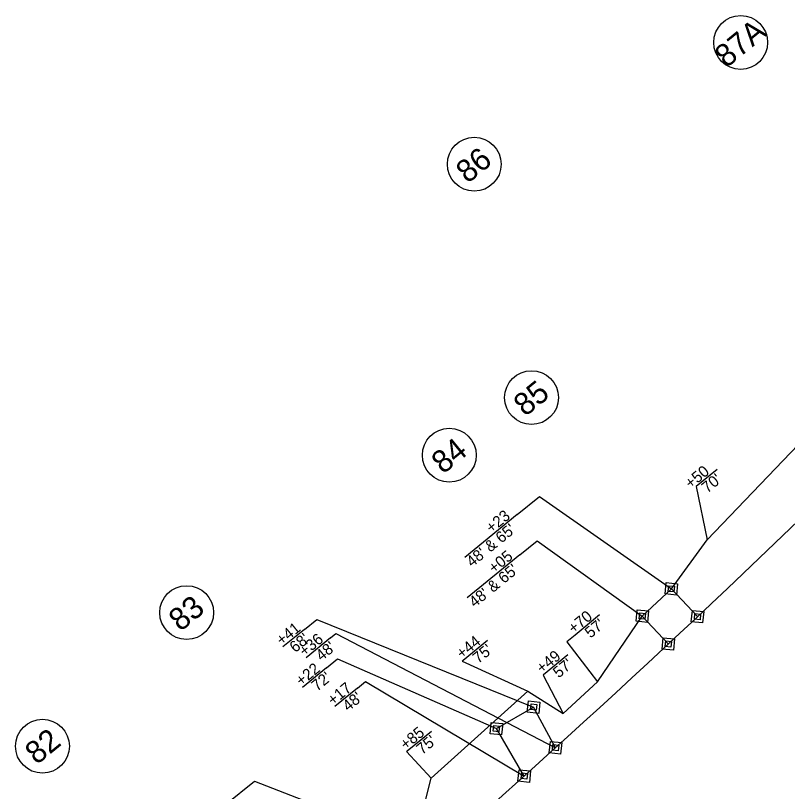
# Model space of a CAD drawing. Extents: x 2320946 to 2332748, y 597838 to 612698.
# Drawn here: x 2326768.2 to 2327112.4, y 602415.6 to 602761.5 of the extents above; entities that cross this region are included whole.
import ezdxf

# ---------------------------------------------------------------- set-up
doc = ezdxf.new("R2010")
doc.units = 0
for name, color, linetype in [('Prop Easement Construction', 7, 'Continuous'), ('Prop Easement Construction Station Offsets', 7, 'Continuous'), ('Prop Easement Permanent Drainage', 7, 'Continuous'), ('Prop Easement Permanent Drainage Station Offsets', 7, 'Continuous'), ('Prop Parcel Number CELL', 7, 'Continuous'), ('Prop ROW Marker CELL', 7, 'Continuous'), ('Prop ROW Permanent Easement CELL', 7, 'Continuous'), ('Prop ROW RW Lines', 7, 'Continuous')]:
    doc.layers.add(name, color=color, linetype=linetype)

msp = doc.modelspace()

# ---------------------------------------------------------------- linework, layer by layer
at = {"layer": 'Prop Easement Construction'}
for p, q in [((2327076.54, 602527.84), (2327251.95, 602710.54)), ((2327060.63, 602505.91), (2327076.54, 602527.84)), ((2327028.65, 602494.3), (2327017.68, 602485.34)), ((2327027.74, 602464.41), (2327047.66, 602493.77)), ((2326978.66, 602482.95), (2326967.74, 602474.04)), ((2327014.46, 602476.53), (2327003.59, 602467.65)), ((2327012.44, 602450.38), (2327027.74, 602464.41)), ((2326953.47, 602421.5), (2326996.67, 602460.36)), ((2326996.67, 602460.36), (2327012.44, 602450.38)), ((2326953.61, 602442.39), (2326942.76, 602433.53)), ((2326946.26, 602392.43), (2326953.47, 602421.5))]:
    msp.add_line(p, q, dxfattribs=at)
for points in [[(2327017.68, 602485.34), (2327013.98, 602482.32), (2327027.74, 602464.41)], [(2326967.74, 602474.04), (2326967.28, 602473.66), (2326996.67, 602460.36)], [(2327003.59, 602467.65), (2327003.41, 602467.51), (2327012.44, 602450.38)], [(2326942.76, 602433.53), (2326942.55, 602433.36), (2326953.47, 602421.5)]]:
    msp.add_lwpolyline(points, dxfattribs=at)
at = {"layer": 'Prop Easement Construction Station Offsets'}
msp.add_line((2327081, 602559.15), (2327071.73, 602551.58), dxfattribs=at)
msp.add_lwpolyline([(2327071.73, 602551.58), (2327076.54, 602527.84)], dxfattribs=at)
at = {"layer": 'Prop Easement Permanent Drainage'}
for p, q in [((2327047.66, 602493.77), (2327060.63, 602505.91)), ((2327060.63, 602505.91), (2327072.27, 602493.53)), ((2327047.66, 602493.77), (2327059.26, 602481.34)), ((2326982.62, 602443.59), (2326999.19, 602453.2)), ((2327008.98, 602435.07), (2326999.19, 602453.2)), ((2326995.02, 602422.45), (2326982.62, 602443.59))]:
    msp.add_line(p, q, dxfattribs=at)
at = {"layer": 'Prop Easement Permanent Drainage Station Offsets'}
for p, q in [((2326991.82, 602539.01), (2326968.47, 602519.95)), ((2326993.01, 602521.03), (2326969.65, 602501.96)), ((2326897, 602487.83), (2326887.46, 602480.04)), ((2326908.68, 602484.13), (2326897.79, 602475.23)), ((2326906.79, 602470.64), (2326896.12, 602461.93)), ((2326920.62, 602461.67), (2326910.55, 602453.45))]:
    msp.add_line(p, q, dxfattribs=at)
for points in [[(2326991.82, 602539.01), (2327001.79, 602547.15), (2327060.63, 602505.91)], [(2326993.01, 602521.03), (2327000.8, 602527.39), (2327047.66, 602493.77)], [(2326897, 602487.83), (2326902.51, 602492.33), (2326999.19, 602453.2)], [(2326908.68, 602484.13), (2326911.02, 602486.04), (2327008.98, 602435.07)], [(2326906.79, 602470.64), (2326911.73, 602474.67), (2326982.62, 602443.59)], [(2326920.62, 602461.67), (2326924.3, 602464.68), (2326995.02, 602422.45)], [(2326861.9, 602409.71), (2326874.72, 602420.17), (2326946.26, 602392.43)]]:
    msp.add_lwpolyline(points, dxfattribs=at)
at = {"layer": 'Prop Parcel Number CELL'}
for p, q in [((2327091.52, 602749.54), (2327091.52, 602749.54)), ((2326972.74, 602695.23), (2326972.74, 602695.23)), ((2326998.28, 602591.18), (2326998.28, 602591.18)), ((2326961.61, 602565.5), (2326961.61, 602565.5)), ((2326844.51, 602495.34), (2326844.51, 602495.34)), ((2326780.21, 602435.76), (2326780.21, 602435.76))]:
    msp.add_line(p, q, dxfattribs=at)
for centre in [(2327091.52, 602749.54), (2326972.74, 602695.23), (2326998.28, 602591.18), (2326961.61, 602565.5), (2326844.51, 602495.34), (2326780.21, 602435.76)]:
    msp.add_circle(centre, 12, dxfattribs=at)
at = {"layer": 'Prop ROW Marker CELL'}
for p, q in [((2327060.63, 602505.91), (2327060.63, 602505.91)), ((2327047.66, 602493.77), (2327047.66, 602493.77)), ((2327072.27, 602493.53), (2327072.27, 602493.53)), ((2327059.26, 602481.34), (2327059.26, 602481.34)), ((2326999.19, 602453.2), (2326999.19, 602453.2)), ((2326982.62, 602443.59), (2326982.62, 602443.59)), ((2327008.98, 602435.07), (2327008.98, 602435.07)), ((2326995.02, 602422.45), (2326995.02, 602422.45))]:
    msp.add_line(p, q, dxfattribs=at)
at = {"layer": 'Prop ROW Permanent Easement CELL'}
for points in [[(2327058.35, 602508.7), (2327063.41, 602508.19), (2327062.9, 602503.12), (2327057.84, 602503.64)], [(2327059.49, 602507.31), (2327062.02, 602507.05), (2327061.76, 602504.52), (2327059.23, 602504.77)], [(2327045.38, 602496.56), (2327050.45, 602496.05), (2327049.94, 602490.98), (2327044.87, 602491.49)], [(2327046.52, 602495.16), (2327049.06, 602494.91), (2327048.8, 602492.38), (2327046.27, 602492.63)], [(2327069.99, 602496.32), (2327075.06, 602495.8), (2327074.55, 602490.74), (2327069.48, 602491.25)], [(2327071.13, 602494.92), (2327073.66, 602494.67), (2327073.41, 602492.13), (2327070.88, 602492.39)], [(2327056.98, 602484.13), (2327062.05, 602483.62), (2327061.54, 602478.55), (2327056.47, 602479.06)], [(2327058.12, 602482.74), (2327060.65, 602482.48), (2327060.4, 602479.95), (2327057.87, 602480.2)], [(2326996.92, 602455.99), (2327001.98, 602455.47), (2327001.47, 602450.41), (2326996.4, 602450.92)], [(2326998.05, 602454.59), (2327000.59, 602454.34), (2327000.33, 602451.8), (2326997.8, 602452.06)], [(2326980.35, 602446.38), (2326985.41, 602445.86), (2326984.9, 602440.8), (2326979.84, 602441.31)], [(2326981.49, 602444.98), (2326984.02, 602444.72), (2326983.76, 602442.19), (2326981.23, 602442.45)], [(2327006.71, 602437.86), (2327011.77, 602437.35), (2327011.26, 602432.28), (2327006.19, 602432.79)], [(2327007.84, 602436.46), (2327010.38, 602436.21), (2327010.12, 602433.68), (2327007.59, 602433.93)], [(2326992.75, 602425.24), (2326997.81, 602424.73), (2326997.3, 602419.66), (2326992.24, 602420.18)], [(2326993.89, 602423.85), (2326996.42, 602423.59), (2326996.16, 602421.06), (2326993.63, 602421.31)]]:
    msp.add_lwpolyline(points, close=True, dxfattribs=at)
at = {"layer": 'Prop ROW RW Lines'}
for radius in [4892, 4988]:
    msp.add_arc((2323721.46, 606057.75), radius, 309.22799, 316.52652, dxfattribs=at)

# ---------------------------------------------------------------- texts
at = {"layer": 'Prop Easement Construction'}
for s, p in [('+70', (2327017.06, 602485.64)), ("57' ", (2327024.55, 602483.69)), ('+44', (2326967.28, 602474.47)), ("75' ", (2326974.56, 602472.34)), ('+49', (2327002.93, 602467.93)), ("57' ", (2327010.36, 602465.92)), ('+85', (2326942.17, 602433.86)), ("75'", (2326949.51, 602431.78))]:
    msp.add_text(s, height=5, rotation=39.228, dxfattribs=at).set_placement(p)
at = {"layer": 'Prop Easement Construction Station Offsets'}
for s, p in [('+50', (2327069.18, 602550.31)), ("70'", (2327076.67, 602548.36))]:
    msp.add_text(s, height=5, rotation=39.228, dxfattribs=at).set_placement(p)
at = {"layer": 'Prop Easement Permanent Drainage Station Offsets'}
for s, p in [('+23', (2326980.4, 602530.5)), ("48' & 65'", (2326971.72, 602515.35)), ('+05', (2326981.57, 602512.5)), ("48' & 65'", (2326972.91, 602497.36)), ('+41', (2326886.94, 602480.43)), ("68' ", (2326892.9, 602477.23)), ('+36', (2326897.11, 602475.49)), ("48' ", (2326904.58, 602473.52)), ('+22', (2326895.62, 602462.32)), ("72' ", (2326902.69, 602460.03)), ('+17', (2326909.78, 602453.63)), ("48' ", (2326916.52, 602451.06))]:
    msp.add_text(s, height=5, rotation=39.228, dxfattribs=at).set_placement(p)
at = {"layer": 'Prop Parcel Number CELL'}
for s, p in [('87A', (2327085.2, 602737.92)), ('86', (2326969.8, 602686.38)), ('85', (2326995.47, 602582.44)), ('84', (2326958.86, 602556.8)), ('83', (2326841.71, 602486.6)), ('82', (2326777.66, 602427.23))]:
    msp.add_text(s, height=10, rotation=39.228, dxfattribs=at).set_placement(p)

doc.saveas('drawing.dxf')
